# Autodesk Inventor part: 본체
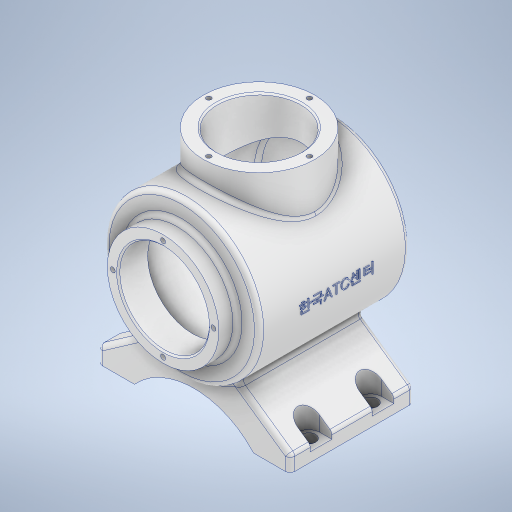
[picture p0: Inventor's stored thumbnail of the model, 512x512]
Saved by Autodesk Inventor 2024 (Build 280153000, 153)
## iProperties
Created: 2023-08
Part Number: 본체
Material: 알루미늄 6061
Document SubType Name: Modeling
Designer: Owner
Density: 2.7 g/cm^3
Appearance: 알루미늄 - 평지
Mass: 1278.64 g
Surface Area: 1055.71 cm^2
Volume: 473.572 cm^3
Author: Owner
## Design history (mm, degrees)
sketch "스케치1"
  geometry: L1 (0, 0)-(36, 0); L2 (36, 0)-(36, -12); L3 (36, -12)-(0, -12); L4 (0, -12)-(0, 0); L5 (0, -12)-(50, -12); L6 (50, -12)-(50, -120); L7 (50, -120)-(0, -120); L8 (0, -120)-(0, -12); A1 r 113 centre (0, -7) between (0, -120) and (50, -108.336); 2 further points
  constraints: 16 end point, 4 parallel, 2 horizontal, 2 perpendicular, 2 point on circle, 1 centre point, 1 midpoint, 1 point on line, 1 vertical alignment
  dimensions: "d6" = 72 diameter of L2 point (0, -6); "d7" = 100 diameter of L6 L8; "d8" = 12 distance of L1.end L2.end; "d9" = 108 distance of L5.end L6.end; "d10" = 113 radius of A1
revolve "회전1" sketch "스케치1" stored, may be unused: angle "d11" = 90 deg
sketch "스케치2"
  geometry: L1 (-50, -108.336)-(-50, -12) reference; L2 (-50, -12)-(-36, -12) reference; L3 (-36, -12)-(-36, 0) reference; L4 (-36, 0)-(36, 0) reference; L5 (36, 0)-(36, -12) reference; L6 (36, -12)-(50, -12) reference; L7 (50, -12)-(50, -108.336) reference; L8 (43, -103.887)-(43, -19); L9 (43, -19)-(29, -19); L10 (29, -19)-(29, 0); L11 (-29, 0)-(-29, -19); L12 (-29, -19)-(-43, -19); L13 (-43, -19)-(-43, -103.887); L14 (29, 0)-(-29, 0); L15 (0, 0)-(0, -113); L16 (50, -108.336)-(-50, -108.336) reference; A1 r 113 centre (0, -7) between (-50, -108.336) and (0, -120) reference; A2 r 113 centre (0, -7) between (0, -120) and (50, -108.336) reference; A3 r 106 centre (0, -7) between (-43, -103.887) and (0, -113); A4 r 106 centre (0, -7) between (0, -113) and (43, -103.887)
  constraints: 16 end point, 4 point on circle, 2 centre point, 2 point on line, 1 collinear, 1 perpendicular, 6 other
  dimensions: "d12" = 7 distance between parallel lines of L7 L8; "d13" = 7 radial gap between concentric circles of A1 A4
revolve "회전2" sketch "스케치2" stored, may be unused: angle "d14" = 90 deg
fillet "모깎기1" dims "d15" = 3
chamfer "모따기1" distance "d16" = 1; stored, may be unused: second distance "d17" = 2, angle "d18" = 45 deg
fillet "모깎기2" dims "d19" = 3
sketch "스케치3"
  geometry: A1 r 32.5 centre (0, 0) between (0, 32.5) and (32.5, 0); 3 further points
  constraints: 4 point on circle, 2 horizontal alignment, 2 vertical alignment, 1 centre point, 1 coincident
  dimensions: "d20" = 65 diameter of A1
hole "구멍1" sketch "스케치3" at (0, 32.5), (32.5, 0), (0, -32.5), (-32.5, 0) diameter "d21" = 3.242; stored, may be unused: countersink angle "d25" = 90 deg, drill point angle "d27" = 118 deg; dims "d22" = 8, "d23" = 4, "d24" = 2, "d26" = 10
node "작업 평면1"
sketch "스케치4"
  geometry: C1 r 36 at (0, -62); 1 further point
  constraints: 1 centre point, 1 vertical alignment
  dimensions: "d29" = 72 diameter of C1; "d30" = 62 distance of point (0, 0) C1.centre
extrude "돌출1" join sketch "스케치4" stored distance "d31" = 10; taper "d32" = 0 deg
sketch "스케치5"
  geometry: C1 r 36 at (0, 0) reference; C2 r 27 at (0, 0); 1 further point
  constraints: 1 centre point, 1 coincident
  dimensions: "d33" = 54 diameter of C2
extrude "돌출2" cut sketch "스케치5" stored distance "d34" = 10; taper "d35" = 0 deg
chamfer "모따기2" distance "d36" = 1; stored, may be unused: second distance "d37" = 2, angle "d38" = 45 deg
sketch "스케치6"
  geometry: C1 r 28 at (0, 0) reference; C2 r 36 at (0, 0) reference; A1 r 32.5 centre (0, 0) between (-32.5, 0) and (0, 32.5); 3 further points
  constraints: 4 point on circle, 2 horizontal alignment, 2 vertical alignment, 1 centre point, 1 coincident
  dimensions: "d39" = 65 diameter of A1
hole "구멍2" sketch "스케치6" at (-32.5, 0), (0, 32.5), (32.5, 0), (0, -32.5) diameter "d40" = 3.242; stored, may be unused: countersink angle "d44" = 90 deg, drill point angle "d46" = 118 deg; dims "d41" = 8, "d42" = 4, "d43" = 2, "d45" = 10
node "작업 평면2"
node "작업 평면3"
sketch "스케치9"
  geometry: L1 (-26.694, -42.278)-(-62, -67); L2 (-62, -67)-(-62, -77); L3 (-62, -77)-(-38.5, -77); L4 (38.5, -77)-(62, -77); L5 (62, -77)-(62, -67); L6 (62, -67)-(26.694, -42.278); A1 r 50 centre (0, 0) between (-26.694, -42.278) and (26.694, -42.278) reference; A2 r 52.096 centre (0, -112.096) between (38.5, -77) and (-38.5, -77); 5 further points
  constraints: 12 end point, 5 point on circle, 3 equal length, 3 midpoint, 2 perpendicular, 1 centre point, 1 horizontal, 1 horizontal alignment, 1 vertical
  dimensions: "d57" = 55 deg angle of L1 L2; "d58" = 55 deg angle of L5 L6; "d59" = 10 distance of L1.end L2.end; "d60" = 77 distance from line of L4 point (0, 0); "d61" = 77 distance of L4.start L3.end; "d62" = 17 vertical distance of point (50.25, -77) point (0, -60); "d63" = 124 distance of point (62, -72) point (-62, -72)
extrude "돌출4" join sketch "스케치9" distance "d64" = 80; taper "d65" = 0 deg
node "작업 평면4"
sketch "스케치10"
  geometry: L1 (23.5, 0)-(23.5, -80) reference; L2 (23.5, -80)-(-6.483, -80) reference; L3 (-6.483, -80)-(-6.483, 0) reference; L4 (-6.483, 0)-(23.5, 0) reference; L5 (-100.5, -80)-(-100.5, 0) reference; L6 (-100.5, 0)-(-70.517, 0) reference; L7 (-70.517, 0)-(-70.517, -80) reference; L8 (-70.517, -80)-(-100.5, -80) reference; L9 (23.5, -13)-(15.5, -13); L10 (15.5, -13)-(15.5, -27); L11 (15.5, -27)-(23.5, -27); L12 (23.5, -27)-(23.5, -13); L13 (23.5, -53)-(15.5, -53); L14 (15.5, -53)-(15.5, -67); L15 (15.5, -67)-(23.5, -67); L16 (23.5, -67)-(23.5, -53); A1 r 7 centre (15.5, -20) between (15.5, -13) and (15.5, -27); A2 r 7 centre (15.5, -60) between (15.5, -53) and (15.5, -67); 3 further points
  constraints: 16 end point, 4 parallel, 4 point on circle, 4 tangent, 3 point on line, 2 centre point, 2 horizontal, 2 midpoint, 2 perpendicular
  dimensions: "d67" = 14 distance of L11.end L9.start; "d68" = 14 distance of L13.end L14.end; "d70" = 20 distance from line of L4 point (15.5, -20); "d71" = 40 distance of point (15.5, -20) point (15.5, -60); "d72" = 8 distance of L10.end L11.end
extrude "돌출5" cut sketch "스케치10" distance "d73" = 30; taper "d74" = 0 deg
sketch "스케치11"
  geometry: L1 (-6.483, -80)-(-6.483, 0) reference; L2 (-6.483, 0)-(23.5, 0) reference; L3 (23.5, 0)-(23.5, -13) reference; L4 (23.5, -13)-(23.5, -27) reference; L5 (15.5, -27)-(23.5, -27) reference; L6 (23.5, -13)-(15.5, -13) reference; L7 (23.5, -80)-(-6.483, -80) reference; L8 (23.5, -67)-(23.5, -80) reference; L9 (15.5, -67)-(23.5, -67) reference; L10 (23.5, -53)-(15.5, -53) reference; L11 (23.5, -53)-(23.5, -67) reference; L12 (23.5, -27)-(23.5, -53) reference; L13 (-100.5, -80)-(-100.5, 0) reference; L14 (-100.5, 0)-(-70.517, 0) reference; L15 (-70.517, 0)-(-70.517, -80) reference; L16 (-70.517, -80)-(-100.5, -80) reference; C1 r 4.5 at (15.5, -20); C2 r 4.5 at (15.5, -60); A1 r 7 centre (15.5, -20) between (15.5, -13) and (15.5, -27) reference; A2 r 7 centre (15.5, -60) between (15.5, -53) and (15.5, -67) reference; 1 further point
  constraints: 2 centre point, 2 coincident
  dimensions: "d75" = 9 diameter of C1; "d76" = 9 diameter of C2
extrude "돌출6" cut sketch "스케치11" distance "d77" = 30; taper "d78" = 0 deg
fillet "모깎기3" dims "d79" = 3
fillet "모깎기4" dims "d80" = 3
fillet "모깎기5" dims "d81" = 3
node "작업 평면5"
sketch "스케치12"
  geometry: 2 further points
  constraints: 1 vertical alignment, 1 other
  dimensions: "d82" = 62 distance of point (0, 60.168) point (0, -1.832)
feature "엠보싱1" sketch "스케치12" dims "d6" = 72, "d7" = 100, "d8" = 12, "d9" = 108, "d10" = 113, "d12" = 7, "d13" = 7, "d83" = 0.5, "d84" = 0
fillet "모깎기6" dims "d85" = 3
node "솔리드1"
mirror "미러1"
node "절단 모서리 투영1"
node "절단 모서리 투영2"
node "절단 모서리 투영3"
node "절단 모서리 투영5"
node "절단 모서리 투영6"
feature "A9D066F2-1C7D-4E18-AEED-F7BC21143FA4" dims "d21" = 3.242, "d22" = 8, "d23" = 4, "d24" = 2, "d25" = 90 deg, "d26" = 10, "d27" = 118 deg
other parameters: "d28" = 65, "d47" = -77, "d66" = -6
